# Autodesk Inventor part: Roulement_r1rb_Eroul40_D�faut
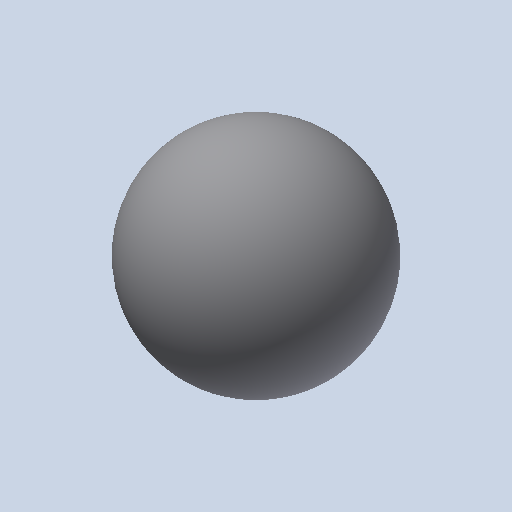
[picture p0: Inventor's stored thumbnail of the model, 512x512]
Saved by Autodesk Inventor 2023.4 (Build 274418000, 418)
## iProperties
Created: 2011-01
Part Number: Roulement_r1rb_Eroul40_D�faut
Document SubType Name: Modeling
Designer: eric
Density: 1 g/cm^3
Mass: 0.172007 g
Surface Area: 1.49571 cm^2
Volume: 0.172007 cm^3
Material: Générique
Appearance: Par défaut
Author: eric
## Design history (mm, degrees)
feature "Base1"
node "Corps solides"
node "Corps surfaciques"
node "Solide1"
